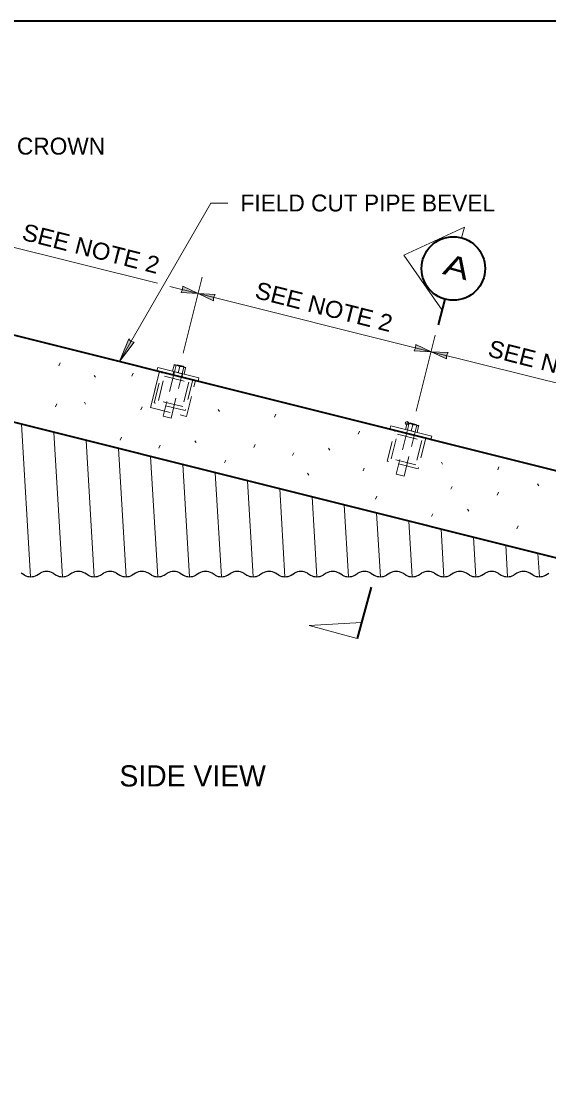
# Model space of a CAD drawing. Extents: x 99860 to 103153, y 99998 to 102077.
# Drawn here: x 101342 to 101840, y 101073 to 102076 of the extents above; entities that cross this region are included whole.
import ezdxf
from ezdxf.enums import TextEntityAlignment as Align

# ---------------------------------------------------------------- set-up
doc = ezdxf.new("R2010")
doc.units = 0
doc.header["$LTSCALE"] = 6.4
doc.header["$PDMODE"] = 32
doc.header["$PDSIZE"] = 3.2
doc.linetypes.add('MEDIUM_DASHED', pattern=[4.5, 3, -1.5])
for name, color, linetype, lineweight in [('1', 7, 'Continuous', 13), ('13', 7, 'Continuous', 40), ('15', 7, 'Continuous', 13), ('17', 7, 'Continuous', 13), ('20', 7, 'Continuous', 13), ('9', 7, 'Continuous', 13)]:
    doc.layers.add(name, color=color, linetype=linetype, lineweight=lineweight)

msp = doc.modelspace()

# ---------------------------------------------------------------- hatches: boundary and pattern name
at = {"layer": '15'}
for points in [[(101509.093, 101818.507), (101494.586, 101825.313), (101494.544, 101822.145), (101493.09, 101819.329)], [(101509.093, 101818.507), (101523.601, 101811.701), (101523.642, 101814.87), (101525.097, 101817.685)], [(101434.811, 101754.401), (101448.81, 101772.679), (101445.696, 101773.255), (101443.64, 101775.664)], [(101728.927, 101763.548), (101714.42, 101770.354), (101714.378, 101767.186), (101712.924, 101764.37)], [(101728.927, 101763.548), (101743.435, 101756.742), (101743.477, 101759.911), (101744.931, 101762.726)]]:
    msp.add_hatch(color=256, dxfattribs=at).paths.add_polyline_path(points)

# ---------------------------------------------------------------- linework, layer by layer
at = {"layer": '1', "linetype": 'MEDIUM_DASHED'}
for p, q in [((100938.07, 101796.125), (101898.063, 101556.125)), ((101267.498, 101796.125), (101472.62, 101744.771)), ((101267.916, 101796.125), (101472.662, 101744.938)), ((101464.173, 101710.983), (101472.62, 101744.771)), ((101467.812, 101715.228), (101475.088, 101744.332)), ((101470.237, 101745.545), (101509.043, 101735.843)), ((101472.62, 101744.771), (101472.662, 101744.938)), ((101475.088, 101744.332), (101504.192, 101737.056)), ((101486.153, 101744.787), (101485.395, 101741.755)), ((101493.884, 101739.633), (101485.395, 101741.755)), ((101486.76, 101744.635), (101486.153, 101744.787)), ((101493.884, 101739.633), (101494.642, 101742.664)), ((101494.642, 101742.664), (101494.036, 101742.816)), ((101471.601, 101717.501), (101477.361, 101740.542)), ((101477.361, 101740.542), (101500.402, 101734.782)), ((101500.402, 101734.782), (101494.642, 101711.741)), ((101504.192, 101737.056), (101496.916, 101707.951)), ((101496.916, 101707.951), (101467.812, 101715.228)), ((101494.642, 101711.741), (101471.601, 101717.501)), ((101687.646, 101660.269), (101694.922, 101689.373)), ((101690.071, 101690.586), (101728.877, 101680.884)), ((101691.435, 101662.542), (101697.196, 101685.583)), ((101694.922, 101689.373), (101724.026, 101682.097)), ((101697.196, 101685.583), (101720.236, 101679.823)), ((101724.026, 101682.097), (101716.75, 101652.993)), ((101726.451, 101681.49), (101912.331, 101635.02)), ((101720.236, 101679.823), (101714.476, 101656.782)), ((101714.476, 101656.782), (101691.435, 101662.542)), ((101716.75, 101652.993), (101687.646, 101660.269))]:
    msp.add_line(p, q, dxfattribs=at)
at = {"layer": '1'}
for p, q in [((101470.995, 101748.576), (101470.237, 101745.545)), ((101509.801, 101738.875), (101470.995, 101748.576)), ((101509.043, 101735.843), (101509.801, 101738.875)), ((101351.12, 101551.125), (101342.487, 101695.02)), ((101690.829, 101693.617), (101690.071, 101690.586)), ((101729.635, 101683.916), (101690.829, 101693.617)), ((101381.12, 101551.125), (101372.944, 101687.406)), ((101728.877, 101680.884), (101729.635, 101683.916)), ((101411.12, 101551.125), (101403.4, 101679.792)), ((101441.12, 101551.125), (101433.857, 101672.177)), ((101471.12, 101551.125), (101464.314, 101664.563)), ((101501.12, 101551.125), (101494.771, 101656.949)), ((101531.12, 101551.125), (101525.228, 101649.335)), ((101561.12, 101551.125), (101555.685, 101641.72)), ((101591.12, 101551.125), (101586.142, 101634.106)), ((101621.12, 101551.125), (101616.598, 101626.492)), ((101651.12, 101551.125), (101647.055, 101618.877)), ((101681.12, 101551.125), (101677.512, 101611.263)), ((101711.12, 101551.125), (101707.969, 101603.649)), ((101741.12, 101551.125), (101738.426, 101596.035)), ((101771.12, 101551.125), (101768.883, 101588.42)), ((101801.12, 101551.125), (101799.34, 101580.806)), ((101831.12, 101551.125), (101829.796, 101573.192))]:
    msp.add_line(p, q, dxfattribs=at)
at = {"layer": '1', "lineweight": 25}
for p, q in [((101345.246, 101552.662), (101342.259, 101554.439)), ((101356.995, 101552.662), (101359.982, 101554.439)), ((101372.259, 101554.439), (101375.246, 101552.662)), ((101389.982, 101554.439), (101386.995, 101552.662)), ((101405.246, 101552.662), (101402.259, 101554.439)), ((101416.995, 101552.662), (101419.982, 101554.439)), ((101432.259, 101554.439), (101435.246, 101552.662)), ((101449.982, 101554.439), (101446.995, 101552.662)), ((101465.246, 101552.662), (101462.259, 101554.439)), ((101476.995, 101552.662), (101479.982, 101554.439)), ((101492.259, 101554.439), (101495.246, 101552.662)), ((101509.982, 101554.439), (101506.995, 101552.662)), ((101525.246, 101552.662), (101522.259, 101554.439)), ((101536.995, 101552.662), (101539.982, 101554.439)), ((101552.259, 101554.439), (101555.246, 101552.662)), ((101569.982, 101554.439), (101566.995, 101552.662)), ((101585.246, 101552.662), (101582.259, 101554.439)), ((101596.995, 101552.662), (101599.982, 101554.439)), ((101612.259, 101554.439), (101615.246, 101552.662)), ((101629.982, 101554.439), (101626.995, 101552.662)), ((101645.246, 101552.662), (101642.259, 101554.439)), ((101656.995, 101552.662), (101659.982, 101554.439)), ((101672.259, 101554.439), (101675.246, 101552.662)), ((101689.982, 101554.439), (101686.995, 101552.662)), ((101705.246, 101552.662), (101702.259, 101554.439)), ((101716.995, 101552.662), (101719.982, 101554.439)), ((101732.259, 101554.439), (101735.246, 101552.662)), ((101749.982, 101554.439), (101746.995, 101552.662)), ((101765.246, 101552.662), (101762.259, 101554.439)), ((101776.995, 101552.662), (101779.982, 101554.439)), ((101792.259, 101554.439), (101795.246, 101552.662)), ((101809.982, 101554.439), (101806.995, 101552.662)), ((101825.246, 101552.662), (101822.259, 101554.439)), ((101836.995, 101552.662), (101839.982, 101554.439))]:
    msp.add_line(p, q, dxfattribs=at)
at = {"layer": '1', "lineweight": 35}
msp.add_lwpolyline([(99862, 99999.5), (103151, 99999.5), (103151, 102075.5), (99862, 102075.5)], close=True, dxfattribs=at)
at = {"layer": '1', "linetype": 'MEDIUM_DASHED'}
for points in [[(101506.617, 101736.449), (101472.662, 101744.938), (101464.173, 101710.983)], [(101464.173, 101710.983), (101498.128, 101702.494), (101506.617, 101736.449), (101692.496, 101689.979)], [(101726.388, 101681.238), (101726.451, 101681.49), (101692.496, 101689.979)]]:
    msp.add_lwpolyline(points, dxfattribs=at)
at = {"layer": '1', "lineweight": 25}
for centre, start, end in [((101351.12, 101563.125), 240.68709, 270), ((101351.12, 101563.125), 270, 299.31291), ((101366.12, 101544.125), 59.24007, 120.75992), ((101381.12, 101563.125), 240.68709, 270), ((101381.12, 101563.125), 270, 299.31291), ((101396.12, 101544.125), 59.24007, 120.75993), ((101411.12, 101563.125), 240.68709, 270), ((101411.12, 101563.125), 270, 299.31291), ((101426.12, 101544.125), 59.24007, 120.75992), ((101441.12, 101563.125), 240.68709, 270), ((101441.12, 101563.125), 270, 299.31291), ((101456.12, 101544.125), 59.24007, 120.75993), ((101471.12, 101563.125), 240.68709, 270), ((101471.12, 101563.125), 270, 299.31291), ((101486.12, 101544.125), 59.24007, 120.75992), ((101501.12, 101563.125), 240.68709, 270), ((101501.12, 101563.125), 270, 299.31291), ((101516.12, 101544.125), 59.24007, 120.75993), ((101531.12, 101563.125), 240.68709, 270), ((101531.12, 101563.125), 270, 299.31291), ((101546.12, 101544.125), 59.24007, 120.75992), ((101561.12, 101563.125), 240.68709, 270), ((101561.12, 101563.125), 270, 299.31291), ((101576.12, 101544.125), 59.24007, 120.75993), ((101591.12, 101563.125), 240.68709, 270), ((101591.12, 101563.125), 270, 299.31291), ((101606.12, 101544.125), 59.24007, 120.75992), ((101621.12, 101563.125), 240.68709, 270), ((101621.12, 101563.125), 270, 299.31291), ((101636.12, 101544.125), 59.24007, 120.75993), ((101651.12, 101563.125), 240.68709, 270), ((101651.12, 101563.125), 270, 299.31291), ((101666.12, 101544.125), 59.24007, 120.75992), ((101681.12, 101563.125), 240.68709, 270), ((101681.12, 101563.125), 270, 299.31291), ((101696.12, 101544.125), 59.24007, 120.75993), ((101711.12, 101563.125), 240.68709, 270), ((101711.12, 101563.125), 270, 299.31291), ((101726.12, 101544.125), 59.24007, 120.75992), ((101741.12, 101563.125), 240.68709, 270), ((101741.12, 101563.125), 270, 299.31291), ((101756.12, 101544.125), 59.24007, 120.75993), ((101771.12, 101563.125), 240.68709, 270), ((101771.12, 101563.125), 270, 299.31291), ((101786.12, 101544.125), 59.24007, 120.75992), ((101801.12, 101563.125), 240.68709, 270), ((101801.12, 101563.125), 270, 299.31291), ((101816.12, 101544.125), 59.24007, 120.75993), ((101831.12, 101563.125), 240.68709, 270), ((101831.12, 101563.125), 270, 299.31291)]:
    msp.add_arc(centre, 12, start, end, dxfattribs=at)
at = {"layer": '13'}
for p, q in [((100899.264, 101888.289), (102226.12, 101556.572)), ((102146.12, 101494.11), (100879.861, 101810.677))]:
    msp.add_line(p, q, dxfattribs=at)
at = {"layer": '15'}
for p, q in [((101434.811, 101754.401), (101521.142, 101903.932)), ((101521.143, 101903.932), (101537.143, 101903.932)), ((101470.703, 101828.105), (101289.259, 101873.466)), ((101512.974, 101834.03), (101495.026, 101762.239)), ((101509.093, 101818.507), (101482.344, 101825.195)), ((101728.927, 101763.548), (101509.093, 101818.507)), ((101732.808, 101779.071), (101714.86, 101707.28)), ((101948.762, 101708.589), (101728.927, 101763.548))]:
    msp.add_line(p, q, dxfattribs=at)
for points in [[(101509.093, 101818.507), (101494.586, 101825.313), (101494.544, 101822.145), (101493.09, 101819.329)], [(101509.093, 101818.507), (101523.601, 101811.701), (101523.642, 101814.87), (101525.097, 101817.685)], [(101434.811, 101754.401), (101448.81, 101772.679), (101445.696, 101773.255), (101443.64, 101775.664)], [(101728.927, 101763.548), (101714.42, 101770.354), (101714.378, 101767.186), (101712.924, 101764.37)], [(101728.927, 101763.548), (101743.435, 101756.742), (101743.477, 101759.911), (101744.931, 101762.726)]]:
    msp.add_lwpolyline(points, close=True, dxfattribs=at)
at = {"layer": '17'}
for p, q in [((101377.591, 101750.341), (101378.831, 101753.111)), ((101411.186, 101741.212), (101412.366, 101739.412)), ((101446.527, 101740.496), (101447.837, 101743.256)), ((101374.61, 101711.591), (101375.86, 101714.361)), ((101401.841, 101715.873), (101403.021, 101714.003)), ((101454.974, 101708.64), (101456.214, 101711.41)), ((101528.024, 101708.918), (101529.204, 101707.048)), ((101581.157, 101701.685), (101582.397, 101704.455)), ((101435.471, 101680.019), (101436.721, 101682.779)), ((101660.145, 101685.849), (101661.455, 101688.609)), ((101471.943, 101672.427), (101473.193, 101675.197)), ((101506.03, 101679.501), (101507.21, 101677.701)), ((101561.655, 101673.064), (101562.905, 101675.824)), ((101632.214, 101672.546), (101633.394, 101670.746)), ((101533.961, 101658.546), (101535.271, 101661.306)), ((101598.126, 101665.472), (101599.376, 101668.242)), ((101664.734, 101650.984), (101665.974, 101653.754)), ((101738.662, 101659.239), (101739.842, 101657.369)), ((101791.795, 101652.007), (101793.035, 101654.777)), ((101612.478, 101648.938), (101613.658, 101647.068)), ((101747.569, 101633.706), (101748.819, 101636.466)), ((101791.296, 101628.222), (101792.606, 101630.982)), ((101829.48, 101638.874), (101830.66, 101637.074)), ((101676.4, 101624.378), (101677.65, 101627.138)), ((101729.278, 101607.845), (101730.528, 101610.615)), ((101763.365, 101614.919), (101764.545, 101613.119)), ((101809.795, 101596.337), (101811.045, 101599.107))]:
    msp.add_line(p, q, dxfattribs=at)
at = {"layer": '9', "lineweight": 35}
for p, q in [((101742.092, 101813.133), (101735.54, 101789.006)), ((101672.357, 101541.143), (101659.253, 101492.89))]:
    msp.add_line(p, q, dxfattribs=at)
at = {"layer": '9'}
for p, q in [((101739.314, 101802.9), (101742.092, 101813.131)), ((101486.532, 101751.456), (101489.163, 101750.799)), ((101488.352, 101751.003), (101486.76, 101744.635)), ((101488.351, 101751.002), (101486.76, 101744.635)), ((101489.35, 101751.289), (101488.373, 101751.009)), ((101489.35, 101751.289), (101494.881, 101749.906)), ((101486.411, 101750.969), (101484.941, 101745.09)), ((101491.867, 101749.606), (101490.397, 101743.726)), ((101494.036, 101742.816), (101495.628, 101749.184)), ((101494.036, 101742.816), (101495.627, 101749.183)), ((101494.588, 101749.442), (101494.846, 101749.378)), ((101494.846, 101749.378), (101497.445, 101748.728)), ((101495.595, 101749.215), (101494.881, 101749.906)), ((101497.323, 101748.242), (101495.853, 101742.362)), ((101706.245, 101696.01), (101704.775, 101690.131)), ((101706.366, 101696.497), (101708.997, 101695.84)), ((101708.186, 101696.044), (101706.594, 101689.676)), ((101708.186, 101696.043), (101706.594, 101689.676)), ((101709.185, 101696.33), (101708.207, 101696.05)), ((101709.185, 101696.33), (101714.715, 101694.947)), ((101711.701, 101694.647), (101710.231, 101688.767)), ((101713.87, 101687.857), (101715.462, 101694.225)), ((101713.87, 101687.857), (101715.462, 101694.224)), ((101714.422, 101694.483), (101714.68, 101694.419)), ((101714.68, 101694.419), (101717.279, 101693.769)), ((101715.429, 101694.256), (101714.715, 101694.947)), ((101717.157, 101693.283), (101715.687, 101687.403))]:
    msp.add_line(p, q, dxfattribs=at)
at = {"layer": '9', "linetype": 'MEDIUM_DASHED'}
for p, q in [((101486.76, 101744.635), (101476.3, 101702.798)), ((101483.576, 101700.979), (101494.036, 101742.816)), ((101486.76, 101744.635), (101494.036, 101742.816)), ((101489.36, 101750.749), (101489.163, 101750.799)), ((101494.846, 101749.378), (101494.588, 101749.442)), ((101483.576, 101700.979), (101476.3, 101702.798)), ((101709.194, 101695.79), (101708.997, 101695.84)), ((101714.68, 101694.419), (101714.422, 101694.483)), ((101706.594, 101689.676), (101696.134, 101647.839)), ((101703.41, 101646.02), (101713.87, 101687.857)), ((101706.594, 101689.676), (101713.87, 101687.857)), ((101703.41, 101646.02), (101696.134, 101647.839))]:
    msp.add_line(p, q, dxfattribs=at)
at = {"layer": '9'}
for points in [[(101757.816, 101871.033), (101760.594, 101881.264), (101703.184, 101854.783), (101739.314, 101802.9)], [(101489.163, 101750.799), (101489.36, 101750.749), (101494.588, 101749.442)], [(101708.997, 101695.84), (101709.194, 101695.79), (101714.422, 101694.483)]]:
    msp.add_lwpolyline(points, dxfattribs=at)
at = {"layer": '9', "linetype": 'MEDIUM_DASHED'}
for points in [[(101484.941, 101745.09), (101490.397, 101743.726), (101495.853, 101742.362)], [(101704.775, 101690.131), (101710.231, 101688.767), (101715.687, 101687.403)]]:
    msp.add_lwpolyline(points, dxfattribs=at)
at = {"layer": '9'}
msp.add_lwpolyline([(101663.322, 101507.873), (101614.01, 101505.176), (101659.253, 101492.89)], close=True, dxfattribs=at)
at = {"layer": '9', "lineweight": 35}
msp.add_circle((101749.953, 101842.083), 30, dxfattribs=at)
at = {"layer": '9'}
msp.add_arc((101749.953, 101842.083), 30, 74.80526, 254.80969, dxfattribs=at)
at = {"layer": '9', "linetype": 'MEDIUM_DASHED'}
for points in [[(101491.867, 101749.605), (101491.001, 101750.156), (101490.059, 101750.6), (101489.07, 101750.819), (101488.207, 101751.01), (101487.303, 101751.037), (101486.41, 101750.969)], [(101488.352, 101751.003), (101488.352, 101751.003), (101488.353, 101751.002), (101488.355, 101751.002), (101488.373, 101750.997), (101488.462, 101750.974), (101488.613, 101750.936), (101488.765, 101750.898), (101488.984, 101750.842), (101489.252, 101750.775), (101489.52, 101750.708), (101489.845, 101750.626), (101490.199, 101750.537), (101490.554, 101750.448), (101490.948, 101750.35), (101491.349, 101750.249), (101491.75, 101750.149), (101492.168, 101750.045), (101492.57, 101749.944), (101492.972, 101749.844), (101493.368, 101749.745), (101493.726, 101749.656), (101493.95, 101749.6), (101494.162, 101749.547), (101494.356, 101749.499)], [(101486.411, 101750.969), (101486.41, 101750.969), (101486.41, 101750.969), (101486.41, 101750.969)], [(101488.565, 101750.948), (101488.614, 101750.936), (101488.67, 101750.921), (101488.734, 101750.905), (101488.916, 101750.859), (101489.164, 101750.797), (101489.456, 101750.724), (101489.748, 101750.65), (101490.093, 101750.564), (101490.463, 101750.471), (101490.832, 101750.379), (101491.236, 101750.278), (101491.642, 101750.176), (101492.047, 101750.075), (101492.465, 101749.97), (101492.86, 101749.872), (101493.255, 101749.773), (101493.639, 101749.677), (101493.98, 101749.592), (101494.321, 101749.507), (101494.628, 101749.431), (101494.876, 101749.369), (101495.103, 101749.313), (101495.287, 101749.267), (101495.413, 101749.236)], [(101495.413, 101749.236), (101495.408, 101749.237), (101495.403, 101749.239), (101495.397, 101749.24), (101495.255, 101749.275), (101495.044, 101749.327), (101494.784, 101749.392), (101494.523, 101749.457), (101494.204, 101749.536), (101493.855, 101749.623), (101493.505, 101749.711), (101493.115, 101749.808), (101492.716, 101749.908), (101492.317, 101750.007), (101491.898, 101750.112), (101491.495, 101750.213), (101491.092, 101750.314), (101490.692, 101750.414), (101490.33, 101750.505), (101490.103, 101750.561), (101489.887, 101750.616), (101489.69, 101750.665), (101489.374, 101750.744), (101489.099, 101750.813), (101488.886, 101750.867), (101488.757, 101750.9), (101488.649, 101750.927), (101488.565, 101750.948)], [(101494.655, 101749.426), (101494.612, 101749.436), (101494.57, 101749.446), (101494.527, 101749.455), (101493.664, 101749.647), (101492.76, 101749.674), (101491.867, 101749.605)], [(101494.356, 101749.499), (101494.665, 101749.422), (101494.933, 101749.355), (101495.137, 101749.304), (101495.341, 101749.254), (101495.488, 101749.218), (101495.564, 101749.199), (101495.606, 101749.189), (101495.627, 101749.184), (101495.627, 101749.184)], [(101497.323, 101748.241), (101496.531, 101748.745), (101495.677, 101749.162), (101494.78, 101749.394)], [(101711.701, 101694.646), (101710.835, 101695.197), (101709.893, 101695.641), (101708.904, 101695.86), (101708.041, 101696.051), (101707.137, 101696.078), (101706.245, 101696.01)], [(101708.186, 101696.044), (101708.186, 101696.044), (101708.187, 101696.043), (101708.189, 101696.043), (101708.207, 101696.038), (101708.296, 101696.015), (101708.447, 101695.977), (101708.599, 101695.939), (101708.818, 101695.883), (101709.086, 101695.816), (101709.354, 101695.749), (101709.679, 101695.667), (101710.034, 101695.578), (101710.388, 101695.489), (101710.782, 101695.391), (101711.183, 101695.291), (101711.584, 101695.19), (101712.002, 101695.086), (101712.404, 101694.985), (101712.806, 101694.885), (101713.203, 101694.786), (101713.56, 101694.697), (101713.784, 101694.641), (101713.997, 101694.588), (101714.19, 101694.54)], [(101708.4, 101695.989), (101708.448, 101695.977), (101708.505, 101695.963), (101708.569, 101695.946), (101708.75, 101695.9), (101708.998, 101695.838), (101709.29, 101695.765), (101709.582, 101695.692), (101709.927, 101695.605), (101710.297, 101695.512), (101710.666, 101695.42), (101711.071, 101695.319), (101711.476, 101695.217), (101711.881, 101695.116), (101712.299, 101695.012), (101712.694, 101694.913), (101713.09, 101694.814), (101713.474, 101694.718), (101713.814, 101694.633), (101714.155, 101694.548), (101714.462, 101694.472), (101714.71, 101694.41), (101714.938, 101694.354), (101715.121, 101694.308), (101715.247, 101694.277)], [(101715.247, 101694.277), (101715.242, 101694.278), (101715.237, 101694.28), (101715.232, 101694.281), (101715.089, 101694.316), (101714.879, 101694.368), (101714.618, 101694.433), (101714.357, 101694.498), (101714.039, 101694.577), (101713.689, 101694.665), (101713.339, 101694.752), (101712.949, 101694.849), (101712.55, 101694.949), (101712.151, 101695.048), (101711.733, 101695.153), (101711.329, 101695.254), (101710.926, 101695.355), (101710.526, 101695.455), (101710.164, 101695.546), (101709.937, 101695.602), (101709.722, 101695.657), (101709.524, 101695.706), (101709.209, 101695.785), (101708.933, 101695.855), (101708.721, 101695.908), (101708.591, 101695.941), (101708.483, 101695.968), (101708.4, 101695.989)], [(101714.489, 101694.467), (101714.447, 101694.477), (101714.404, 101694.487), (101714.361, 101694.496), (101713.498, 101694.688), (101712.594, 101694.715), (101711.701, 101694.646)], [(101714.19, 101694.54), (101714.499, 101694.463), (101714.767, 101694.396), (101714.971, 101694.345), (101715.176, 101694.295), (101715.322, 101694.259), (101715.398, 101694.24), (101715.44, 101694.23), (101715.461, 101694.225), (101715.462, 101694.225)], [(101717.157, 101693.283), (101716.365, 101693.786), (101715.512, 101694.203), (101714.614, 101694.435)]]:
    msp.add_open_spline(points, degree=3, dxfattribs=at)
at = {"layer": '9'}
for points in [[(101486.532, 101751.456), (101486.532, 101751.456), (101486.529, 101751.445), (101486.524, 101751.422), (101486.507, 101751.355), (101486.466, 101751.19), (101486.411, 101750.969)], [(101486.411, 101750.969), (101486.428, 101751.039), (101486.444, 101751.104), (101486.459, 101751.162), (101486.505, 101751.346), (101486.532, 101751.456), (101486.532, 101751.456)], [(101486.411, 101750.969), (101487.335, 101751.04), (101488.272, 101751.008), (101489.163, 101750.799)], [(101495.627, 101749.184), (101495.627, 101749.184), (101495.614, 101749.188), (101495.587, 101749.195), (101495.526, 101749.21), (101495.395, 101749.243), (101495.205, 101749.291), (101495.015, 101749.34), (101494.759, 101749.404), (101494.46, 101749.479), (101494.161, 101749.554), (101493.811, 101749.642), (101493.437, 101749.735), (101493.064, 101749.829), (101492.657, 101749.931), (101492.251, 101750.032), (101491.845, 101750.134), (101491.428, 101750.238), (101491.035, 101750.336), (101490.642, 101750.434), (101490.262, 101750.529), (101489.927, 101750.613), (101489.591, 101750.696), (101489.291, 101750.771), (101489.051, 101750.83), (101488.811, 101750.89), (101488.625, 101750.936), (101488.507, 101750.965), (101488.404, 101750.99), (101488.352, 101751.003), (101488.352, 101751.003)], [(101489.36, 101750.749), (101489.39, 101750.741), (101489.42, 101750.733), (101489.449, 101750.725), (101490.301, 101750.488), (101491.111, 101750.087), (101491.867, 101749.606)], [(101491.867, 101749.606), (101492.781, 101749.676), (101493.706, 101749.646), (101494.588, 101749.442)], [(101494.846, 101749.378), (101494.865, 101749.373), (101494.885, 101749.367), (101494.905, 101749.362), (101495.757, 101749.124), (101496.568, 101748.723), (101497.323, 101748.242)], [(101497.323, 101748.242), (101497.341, 101748.312), (101497.357, 101748.377), (101497.371, 101748.434), (101497.415, 101748.609), (101497.442, 101748.717), (101497.445, 101748.728)], [(101706.366, 101696.497), (101706.366, 101696.497), (101706.364, 101696.486), (101706.358, 101696.463), (101706.341, 101696.396), (101706.3, 101696.231), (101706.245, 101696.01)], [(101706.245, 101696.01), (101706.262, 101696.081), (101706.278, 101696.145), (101706.293, 101696.203), (101706.339, 101696.387), (101706.366, 101696.497), (101706.366, 101696.497)], [(101706.245, 101696.01), (101707.169, 101696.082), (101708.106, 101696.049), (101708.997, 101695.84)], [(101715.462, 101694.225), (101715.462, 101694.225), (101715.448, 101694.229), (101715.421, 101694.236), (101715.361, 101694.251), (101715.23, 101694.284), (101715.039, 101694.333), (101714.849, 101694.381), (101714.593, 101694.445), (101714.295, 101694.52), (101713.996, 101694.595), (101713.645, 101694.683), (101713.271, 101694.776), (101712.898, 101694.87), (101712.491, 101694.972), (101712.085, 101695.073), (101711.679, 101695.175), (101711.262, 101695.279), (101710.869, 101695.377), (101710.476, 101695.475), (101710.096, 101695.57), (101709.761, 101695.654), (101709.426, 101695.737), (101709.125, 101695.812), (101708.885, 101695.871), (101708.645, 101695.931), (101708.459, 101695.977), (101708.341, 101696.006), (101708.239, 101696.032), (101708.186, 101696.044), (101708.186, 101696.044)], [(101709.194, 101695.79), (101709.224, 101695.783), (101709.254, 101695.774), (101709.283, 101695.766), (101710.135, 101695.529), (101710.946, 101695.128), (101711.701, 101694.647)], [(101711.701, 101694.647), (101712.615, 101694.717), (101713.541, 101694.687), (101714.422, 101694.483)], [(101714.68, 101694.419), (101714.7, 101694.414), (101714.719, 101694.408), (101714.739, 101694.403), (101715.591, 101694.165), (101716.402, 101693.764), (101717.157, 101693.283)], [(101717.157, 101693.283), (101717.175, 101693.353), (101717.191, 101693.418), (101717.205, 101693.475), (101717.249, 101693.65), (101717.276, 101693.758), (101717.279, 101693.769)]]:
    msp.add_open_spline(points, degree=3, dxfattribs=at)
msp.add_point((101706.245, 101696.01), dxfattribs=at)

# ---------------------------------------------------------------- texts
at = {"layer": '20'}
for s, p in [('CULVERT CROWN', (101232.367, 101949.631)), ('FIELD CUT PIPE BEVEL', (101549.143, 101895.932))]:
    msp.add_text(s, height=16, dxfattribs=at).set_placement(p)
for s, height, rotation, width, p in [('SEE NOTE 2', 16, 345.776, 1.05, (101406.078, 101853.149)), ('A', 20, 344.807, 1.35, (101750.582, 101834.018)), ('SEE NOTE 2', 16, 345.776, 1.05, (101625.912, 101798.19)), ('SEE NOTE 2', 16, 345.776, 1.05, (101845.746, 101743.231))]:
    msp.add_text(s, height=height, rotation=rotation, dxfattribs=dict(at, width=width)).set_placement(p, align=Align.CENTER)
msp.add_text('SIDE VIEW', height=20, dxfattribs=at).set_placement((101503.97, 101353.144), align=Align.CENTER)

doc.saveas('drawing.dxf')
